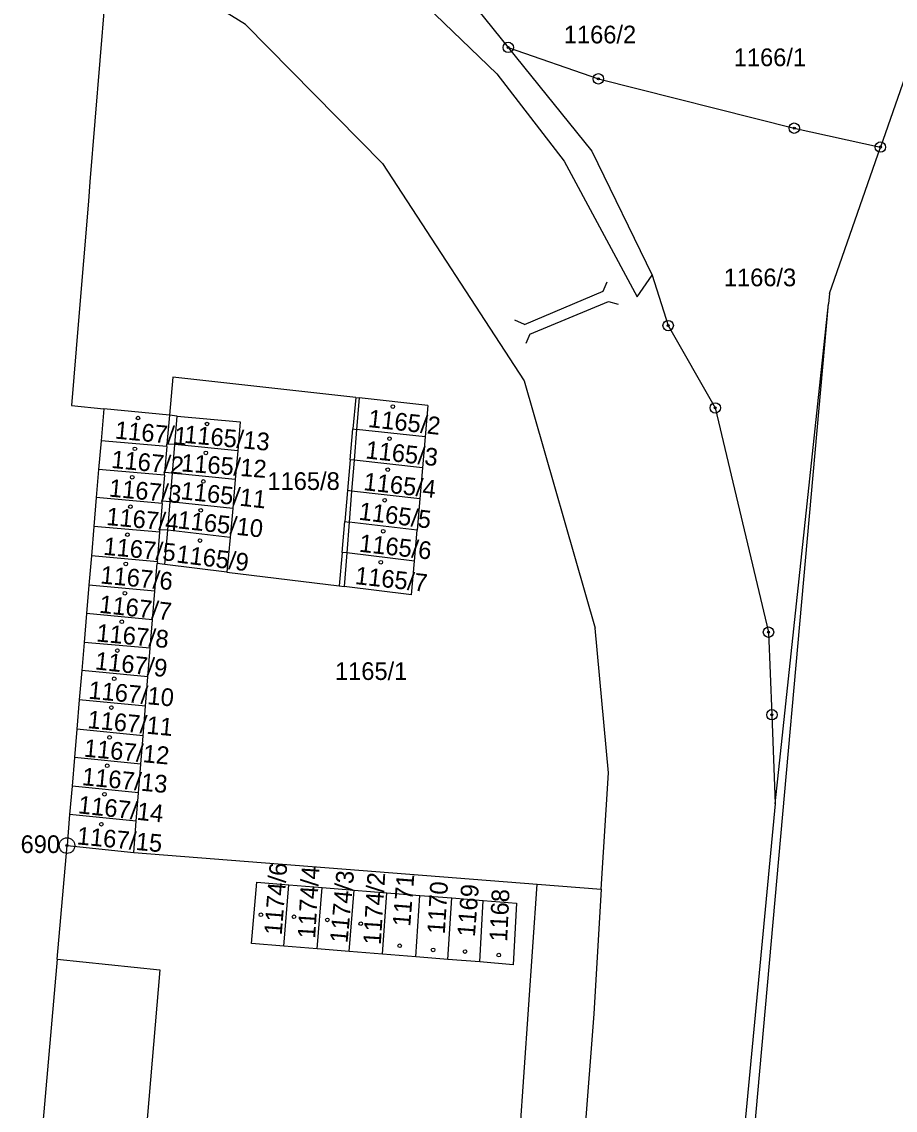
# Model space of a CAD drawing. Extents: x -755819 to -753140, y -1169796 to -1166000.
# Drawn here: x -755317.6 to -755233.7, y -1167073.2 to -1166968.6 of the extents above; entities that cross this region are included whole.
import ezdxf

# ---------------------------------------------------------------- set-up
doc = ezdxf.new("R2010")
doc.units = 0
for name, color, linetype in [('Vrstva 1', 7, 'Continuous'), ('Vrstva 16', 7, 'Continuous'), ('Vrstva 17', 7, 'Continuous'), ('Vrstva 18', 7, 'Continuous'), ('Vrstva 19', 7, 'Continuous'), ('Vrstva 24', 7, 'Continuous'), ('Vrstva 25', 7, 'Continuous'), ('Vrstva 26', 7, 'Continuous'), ('Vrstva 4', 7, 'Continuous')]:
    doc.layers.add(name, color=color, linetype=linetype)

msp = doc.modelspace()

# ---------------------------------------------------------------- linework, layer by layer
at = {"layer": 'Vrstva 1'}
for p, q in [((-755292.45, -1166953.89), (-755271.98, -1166973.65)), ((-755296.14, -1166968.9), (-755307.01, -1166962.12)), ((-755309.64, -1166966.5), (-755311.08, -1166984.02)), ((-755273.83, -1166967.44), (-755270.88, -1166971.1)), ((-755296.14, -1166968.9), (-755282.97, -1166982.25)), ((-755230.79, -1166968.28), (-755235.11, -1166980.67)), ((-755270.88, -1166971.1), (-755262.22, -1166974.12)), ((-755270.88, -1166971.1), (-755262.83, -1166981.07)), ((-755271.98, -1166973.65), (-755265.49, -1166982.02)), ((-755262.22, -1166974.12), (-755243.39, -1166978.86)), ((-755243.39, -1166978.86), (-755235.11, -1166980.67)), ((-755240.01, -1166994.75), (-755235.11, -1166980.67)), ((-755262.83, -1166981.07), (-755257.06, -1166992.97)), ((-755282.97, -1166982.25), (-755269.36, -1167003.13)), ((-755265.49, -1166982.02), (-755258.5, -1166995.05)), ((-755311.08, -1166984.02), (-755311.23, -1166985.86)), ((-755311.23, -1166985.86), (-755312.18, -1166997.35)), ((-755258.5, -1166995.05), (-755257.06, -1166992.97)), ((-755257.06, -1166992.97), (-755255.51, -1166997.83)), ((-755240.01, -1166994.75), (-755240.09, -1166995.74)), ((-755257.07, -1167185.13), (-755240.09, -1166995.74)), ((-755245.22, -1167043.79), (-755240.09, -1166995.74)), ((-755312.18, -1166997.35), (-755312.86, -1167005.51)), ((-755255.51, -1166997.83), (-755250.99, -1167005.74)), ((-755303.12, -1167002.77), (-755303.44, -1167006.45)), ((-755285.54, -1167004.73), (-755303.12, -1167002.77)), ((-755269.36, -1167003.13), (-755262.52, -1167026.89)), ((-755285.54, -1167004.73), (-755285.81, -1167007.75)), ((-755285.54, -1167004.73), (-755285.22, -1167004.76)), ((-755278.6, -1167005.5), (-755285.22, -1167004.76)), ((-755312.86, -1167005.51), (-755309.75, -1167005.82)), ((-755278.6, -1167005.5), (-755278.86, -1167008.51)), ((-755250.99, -1167005.74), (-755245.87, -1167027.29)), ((-755309.75, -1167005.82), (-755310.01, -1167008.91)), ((-755303.44, -1167006.45), (-755309.75, -1167005.82)), ((-755303.44, -1167006.45), (-755303.68, -1167009.22)), ((-755302.68, -1167006.54), (-755303.44, -1167006.45)), ((-755302.68, -1167006.54), (-755296.63, -1167007.09)), ((-755296.63, -1167007.09), (-755296.87, -1167009.85)), ((-755286.07, -1167010.72), (-755285.81, -1167007.75)), ((-755285.81, -1167007.75), (-755285.46, -1167007.8)), ((-755278.86, -1167008.51), (-755285.46, -1167007.8)), ((-755310.01, -1167008.91), (-755310.24, -1167011.65)), ((-755303.69, -1167009.46), (-755310.01, -1167008.91)), ((-755278.86, -1167008.51), (-755279.12, -1167011.5)), ((-755303.69, -1167009.46), (-755303.9, -1167011.96)), ((-755303.69, -1167009.46), (-755303.68, -1167009.22)), ((-755302.91, -1167009.27), (-755303.68, -1167009.22)), ((-755296.87, -1167009.85), (-755302.91, -1167009.27)), ((-755296.87, -1167009.85), (-755297.12, -1167012.63)), ((-755286.07, -1167010.72), (-755286.33, -1167013.69)), ((-755285.69, -1167010.77), (-755286.07, -1167010.72)), ((-755279.12, -1167011.5), (-755285.69, -1167010.77)), ((-755310.24, -1167011.65), (-755310.47, -1167014.36)), ((-755303.91, -1167012.21), (-755310.24, -1167011.65)), ((-755303.91, -1167012.21), (-755303.9, -1167011.96)), ((-755303.14, -1167012.01), (-755303.9, -1167011.96)), ((-755297.12, -1167012.63), (-755303.14, -1167012.01)), ((-755279.12, -1167011.5), (-755279.38, -1167014.49)), ((-755303.91, -1167012.21), (-755304.12, -1167014.7)), ((-755297.12, -1167012.63), (-755297.36, -1167015.41)), ((-755286.33, -1167013.69), (-755286.59, -1167016.66)), ((-755285.93, -1167013.74), (-755286.33, -1167013.69)), ((-755279.38, -1167014.49), (-755285.93, -1167013.74)), ((-755310.47, -1167014.36), (-755310.7, -1167017.12)), ((-755304.14, -1167014.93), (-755310.47, -1167014.36)), ((-755304.14, -1167014.93), (-755304.35, -1167017.44)), ((-755304.14, -1167014.93), (-755304.12, -1167014.7)), ((-755303.36, -1167014.75), (-755304.12, -1167014.7)), ((-755297.36, -1167015.41), (-755303.36, -1167014.75)), ((-755279.38, -1167014.49), (-755279.64, -1167017.47)), ((-755297.36, -1167015.41), (-755297.61, -1167018.18)), ((-755310.7, -1167017.12), (-755310.94, -1167019.94)), ((-755304.36, -1167017.69), (-755310.7, -1167017.12)), ((-755286.85, -1167019.63), (-755286.59, -1167016.66)), ((-755286.59, -1167016.66), (-755286.16, -1167016.71)), ((-755279.64, -1167017.47), (-755286.16, -1167016.71)), ((-755304.6, -1167020.53), (-755304.36, -1167017.69)), ((-755304.36, -1167017.69), (-755304.35, -1167017.44)), ((-755303.59, -1167017.49), (-755304.35, -1167017.44)), ((-755297.61, -1167018.18), (-755303.59, -1167017.49)), ((-755297.61, -1167018.18), (-755297.91, -1167021.52)), ((-755279.9, -1167020.46), (-755279.64, -1167017.47)), ((-755310.94, -1167019.94), (-755311.18, -1167022.76)), ((-755304.6, -1167020.53), (-755310.94, -1167019.94)), ((-755286.85, -1167019.63), (-755287.13, -1167022.85)), ((-755286.4, -1167019.68), (-755286.85, -1167019.63)), ((-755279.9, -1167020.46), (-755286.4, -1167019.68)), ((-755304.83, -1167023.35), (-755304.61, -1167020.7)), ((-755304.6, -1167020.53), (-755304.61, -1167020.7)), ((-755303.87, -1167020.79), (-755304.61, -1167020.7)), ((-755297.91, -1167021.52), (-755303.87, -1167020.79)), ((-755280.18, -1167023.71), (-755279.9, -1167020.46)), ((-755297.91, -1167021.52), (-755287.13, -1167022.85)), ((-755311.18, -1167022.76), (-755311.41, -1167025.5)), ((-755304.83, -1167023.35), (-755311.18, -1167022.76)), ((-755305.05, -1167026.1), (-755304.83, -1167023.35)), ((-755287.13, -1167022.85), (-755286.65, -1167022.91)), ((-755280.18, -1167023.71), (-755286.65, -1167022.91)), ((-755311.41, -1167025.5), (-755311.64, -1167028.28)), ((-755305.05, -1167026.1), (-755311.41, -1167025.5)), ((-755305.28, -1167028.83), (-755305.05, -1167026.1)), ((-755261.26, -1167040.79), (-755262.52, -1167026.89)), ((-755245.87, -1167027.29), (-755245.54, -1167035.22)), ((-755311.64, -1167028.28), (-755311.87, -1167030.97)), ((-755305.28, -1167028.83), (-755311.64, -1167028.28)), ((-755305.5, -1167031.58), (-755305.28, -1167028.83)), ((-755311.87, -1167030.97), (-755312.1, -1167033.79)), ((-755305.5, -1167031.58), (-755311.87, -1167030.97)), ((-755305.74, -1167034.41), (-755305.5, -1167031.58)), ((-755312.1, -1167033.79), (-755312.34, -1167036.61)), ((-755305.74, -1167034.41), (-755312.1, -1167033.79)), ((-755305.97, -1167037.24), (-755305.74, -1167034.41)), ((-755245.54, -1167035.22), (-755245.22, -1167043.79)), ((-755312.34, -1167036.61), (-755312.57, -1167039.33)), ((-755305.97, -1167037.24), (-755312.34, -1167036.61)), ((-755306.19, -1167039.97), (-755305.97, -1167037.24)), ((-755312.57, -1167039.33), (-755312.8, -1167042.07)), ((-755306.19, -1167039.97), (-755312.57, -1167039.33)), ((-755306.42, -1167042.71), (-755306.19, -1167039.97)), ((-755261.94, -1167051.98), (-755261.26, -1167040.79)), ((-755312.8, -1167042.07), (-755313.03, -1167044.81)), ((-755306.42, -1167042.71), (-755312.8, -1167042.07)), ((-755306.64, -1167045.45), (-755306.42, -1167042.71)), ((-755245.22, -1167043.79), (-755256.7, -1167164.07)), ((-755313.03, -1167044.81), (-755313.28, -1167047.79)), ((-755306.64, -1167045.45), (-755313.03, -1167044.81)), ((-755306.87, -1167048.45), (-755306.64, -1167045.45)), ((-755314.23, -1167058.72), (-755313.28, -1167047.79)), ((-755313.28, -1167047.79), (-755306.87, -1167048.45)), ((-755306.87, -1167048.45), (-755268.09, -1167051.5)), ((-755295.56, -1167057.21), (-755295.04, -1167051.31)), ((-755295.04, -1167051.31), (-755291.95, -1167051.56)), ((-755292.44, -1167057.46), (-755291.95, -1167051.56)), ((-755291.95, -1167051.56), (-755288.77, -1167051.82)), ((-755289.24, -1167057.72), (-755288.77, -1167051.82)), ((-755288.77, -1167051.82), (-755285.68, -1167052.07)), ((-755272.16, -1167110.38), (-755268.09, -1167051.5)), ((-755268.09, -1167051.5), (-755261.94, -1167051.98)), ((-755286.15, -1167057.97), (-755285.68, -1167052.07)), ((-755285.68, -1167052.07), (-755282.53, -1167052.32)), ((-755282.95, -1167058.23), (-755282.53, -1167052.32)), ((-755282.53, -1167052.32), (-755279.38, -1167052.58)), ((-755279.76, -1167058.49), (-755279.38, -1167052.58)), ((-755279.38, -1167052.58), (-755276.31, -1167052.82)), ((-755276.69, -1167058.74), (-755276.31, -1167052.82)), ((-755276.31, -1167052.82), (-755273.28, -1167053.07)), ((-755261.94, -1167051.98), (-755262.66, -1167063.96)), ((-755273.61, -1167058.98), (-755273.28, -1167053.07)), ((-755273.28, -1167053.07), (-755270.08, -1167053.33)), ((-755270.08, -1167053.33), (-755270.41, -1167059.24)), ((-755292.44, -1167057.46), (-755295.56, -1167057.21)), ((-755289.24, -1167057.72), (-755292.44, -1167057.46)), ((-755286.15, -1167057.97), (-755289.24, -1167057.72)), ((-755282.95, -1167058.23), (-755286.15, -1167057.97)), ((-755314.23, -1167058.72), (-755315.67, -1167075.2)), ((-755314.23, -1167058.72), (-755304.37, -1167059.74)), ((-755279.76, -1167058.49), (-755282.95, -1167058.23)), ((-755276.69, -1167058.74), (-755279.76, -1167058.49)), ((-755273.61, -1167058.98), (-755276.69, -1167058.74)), ((-755270.41, -1167059.24), (-755273.61, -1167058.98)), ((-755304.37, -1167059.74), (-755305.72, -1167075.88)), ((-755262.66, -1167063.96), (-755267.72, -1167130.91))]:
    msp.add_line(p, q, dxfattribs=at)
at = {"layer": 'Vrstva 24'}
for centre, radius in [((-755270.88, -1166971.1), 0.5), ((-755270.88, -1166971.1), 0.1), ((-755262.22, -1166974.12), 0.5), ((-755262.22, -1166974.12), 0.1), ((-755243.39, -1166978.86), 0.5), ((-755243.39, -1166978.86), 0.1), ((-755235.11, -1166980.67), 0.5), ((-755235.11, -1166980.67), 0.1), ((-755255.51, -1166997.83), 0.5), ((-755255.51, -1166997.83), 0.1), ((-755250.99, -1167005.74), 0.5), ((-755250.99, -1167005.74), 0.1), ((-755245.87, -1167027.29), 0.5), ((-755245.87, -1167027.29), 0.1), ((-755245.54, -1167035.22), 0.5), ((-755245.54, -1167035.22), 0.1), ((-755313.28, -1167047.79), 0.75), ((-755313.28, -1167047.79), 0.1)]:
    msp.add_circle(centre, radius, dxfattribs=at)
at = {"layer": 'Vrstva 25'}
for centre in [(-755281.97, -1167005.61), (-755306.46, -1167006.71), (-755299.83, -1167007.28), (-755282.29, -1167008.69), (-755306.76, -1167009.67), (-755299.94, -1167010.06), (-755282.46, -1167011.67), (-755307.01, -1167012.4), (-755300.18, -1167012.8), (-755307.18, -1167015.23), (-755282.75, -1167014.61), (-755300.43, -1167015.58), (-755307.47, -1167017.92), (-755300.5, -1167018.49), (-755282.89, -1167017.59), (-755283.13, -1167020.57), (-755307.63, -1167020.73), (-755307.72, -1167023.55), (-755308.02, -1167026.29), (-755308.44, -1167029.06), (-755308.74, -1167031.76), (-755309.02, -1167034.53), (-755309.19, -1167037.4), (-755309.41, -1167040.13), (-755309.68, -1167042.86), (-755309.98, -1167045.74), (-755294.65, -1167054.44), (-755291.47, -1167054.64), (-755288.26, -1167054.94), (-755285.05, -1167055.3), (-755281.31, -1167057.42), (-755278.1, -1167057.82), (-755275.03, -1167057.98), (-755271.79, -1167058.32)]:
    msp.add_circle(centre, 0.175, dxfattribs=at)
at = {"layer": 'Vrstva 26'}
for p, q in [((-755261.75, -1166994.53), (-755261.36, -1166993.61)), ((-755261.26, -1166995.51), (-755260.3, -1166995.77)), ((-755269.32, -1166997.72), (-755270.23, -1166997.31)), ((-755268.81, -1166998.64), (-755269.2, -1166999.56))]:
    msp.add_line(p, q, dxfattribs=at)
at = {"layer": 'Vrstva 4'}
for p, q in [((-755269.32, -1166997.72), (-755261.75, -1166994.53)), ((-755268.81, -1166998.64), (-755261.26, -1166995.51)), ((-755285.22, -1167004.76), (-755285.46, -1167007.8)), ((-755302.91, -1167009.27), (-755302.68, -1167006.54)), ((-755285.46, -1167007.8), (-755285.69, -1167010.77)), ((-755303.14, -1167012.01), (-755302.91, -1167009.27)), ((-755285.69, -1167010.77), (-755285.93, -1167013.74)), ((-755303.36, -1167014.75), (-755303.14, -1167012.01)), ((-755285.93, -1167013.74), (-755286.16, -1167016.71)), ((-755303.59, -1167017.49), (-755303.36, -1167014.75)), ((-755286.16, -1167016.71), (-755286.4, -1167019.68)), ((-755303.87, -1167020.79), (-755303.59, -1167017.49)), ((-755286.4, -1167019.68), (-755286.65, -1167022.91))]:
    msp.add_line(p, q, dxfattribs=at)

# ---------------------------------------------------------------- texts
at = {"layer": 'Vrstva 16'}
msp.add_text('1166/2', height=1.7, dxfattribs=at).set_placement((-755265.54, -1166970.71))
at = {"layer": 'Vrstva 17'}
msp.add_text('690', height=1.7, dxfattribs=at).set_placement((-755317.74, -1167048.51))
at = {"layer": 'Vrstva 18'}
for s, p in [('1166/1', (-755249.21, -1166972.9)), ('1166/3', (-755250.16, -1166994.05)), ('1165/8', (-755294.02, -1167013.62)), ('1165/1', (-755287.53, -1167031.88))]:
    msp.add_text(s, height=1.7, dxfattribs=at).set_placement(p)
at = {"layer": 'Vrstva 19'}
for s, rotation, p in [('1165/2', 353.6868, (-755284.4, -1167007.57)), ('1167/1', 354.6036, (-755308.72, -1167008.68)), ('1165/13', 354.6036, (-755302.07, -1167009.09)), ('1167/2', 354.6036, (-755309.07, -1167011.5)), ('1165/3', 353.6868, (-755284.65, -1167010.58)), ('1165/12', 355.5203, (-755302.36, -1167011.83)), ('1165/4', 353.6868, (-755284.84, -1167013.63)), ('1167/3', 354.6036, (-755309.3, -1167014.25)), ('1165/11', 353.6868, (-755302.41, -1167014.5)), ('1165/5', 352.8274, (-755285.3, -1167016.47)), ('1167/4', 354.6036, (-755309.56, -1167016.98)), ('1165/10', 353.6868, (-755302.71, -1167017.3)), ('1167/5', 354.6036, (-755309.83, -1167019.84)), ('1165/6', 353.6868, (-755285.26, -1167019.55)), ('1165/9', 352.8274, (-755302.83, -1167020.58)), ('1167/6', 354.6036, (-755310.12, -1167022.6)), ('1165/7', 353.6868, (-755285.66, -1167022.66)), ('1167/7', 353.6868, (-755310.24, -1167025.41)), ('1167/8', 354.6036, (-755310.51, -1167028.17)), ('1167/9', 353.6868, (-755310.65, -1167030.85)), ('1167/10', 354.6036, (-755311.27, -1167033.67)), ('1167/11', 354.6036, (-755311.36, -1167036.5)), ('1167/12', 354.6036, (-755311.71, -1167039.24)), ('1167/13', 354.6036, (-755311.89, -1167041.98)), ('1167/14', 353.6868, (-755312.28, -1167044.68)), ('1167/15', 354.6036, (-755312.39, -1167047.67)), ('1174/6', 85.4853, (-755292.65, -1167056.44)), ('1174/4', 86.402, (-755289.44, -1167056.77)), ('1174/3', 84.6259, (-755286.33, -1167057.2)), ('1174/2', 86.402, (-755283.13, -1167057.37)), ('1171', 85.4853, (-755280.3, -1167055.62)), ('1170', 86.402, (-755276.98, -1167056.34)), ('1169', 85.4853, (-755274.09, -1167056.61)), ('1168', 87.3188, (-755270.99, -1167057.06))]:
    msp.add_text(s, height=1.7, rotation=rotation, dxfattribs=at).set_placement(p)

doc.saveas('drawing.dxf')
